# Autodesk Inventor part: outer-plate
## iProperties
Shininess: 64.0
Length Units: 11269
Angle Units: 11279
Time Units: 11290
Mass Units: 11283
Length Display Precision: 3
Angle Display Precision: 2
Compacted: True
Part Number: outer-plate
Document SubType Name: Modeling
Created: 2003-11
Designer: Owner
Manufacturer: Standard
Standards Organization: Custom
Density: 1 g/cm^3
Density: 0.0
Volumn: 0.0
Area: 0.0
PropertySet Name: Model Information
Control State: 0
Master: False
Checked Out: False
Author: Owner
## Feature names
1. Extrusion1
